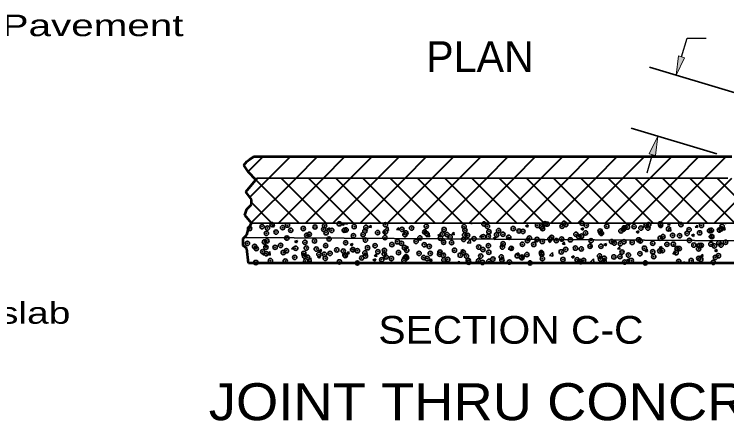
# Model space of a CAD drawing. Extents: x 14 to 49.3, y 28 to 50.
# Drawn here: x 24.379 to 29.004, y 39.461 to 42.098 of the extents above; entities that cross this region are included whole.
import ezdxf

# ---------------------------------------------------------------- set-up
doc = ezdxf.new("R2010")
doc.units = 0
doc.header["$LTSCALE"] = 0.056
doc.header["$PDMODE"] = 32
doc.header["$PDSIZE"] = 0.028
for name, color, linetype, lineweight in [('1', 7, 'Continuous', 35), ('3', 7, 'Continuous', 13), ('6', 7, 'Continuous', 13)]:
    doc.layers.add(name, color=color, linetype=linetype, lineweight=lineweight)

msp = doc.modelspace()

# ---------------------------------------------------------------- hatches: boundary and pattern name
at = {"layer": '1'}
for points in [[(28.72983, 41.81658), (28.68992, 41.8285), (28.67417, 41.70283), (28.67417, 41.70283)], [(28.54042, 41.18158), (28.5005, 41.1935), (28.55617, 41.30733), (28.55617, 41.30733)]]:
    msp.add_hatch(color=256, dxfattribs=at).paths.add_polyline_path(points)

# ---------------------------------------------------------------- linework, layer by layer
at = {"layer": '1', "lineweight": 25}
for p, q in [((28.70983, 41.82258), (28.74558, 41.94233)), ((28.74558, 41.94233), (28.87058, 41.94233)), ((28.52042, 41.1875), (28.48467, 41.06775))]:
    msp.add_line(p, q, dxfattribs=at)
at = {"layer": '1'}
for p, q in [((29.05775, 41.58833), (28.50167, 41.75425)), ((28.93975, 41.19292), (28.38367, 41.35875)), ((25.95442, 41.0355), (29.01067, 41.0355)), ((25.91817, 40.74367), (29.60692, 40.74367)), ((26.0495, 40.72508), (26.067, 40.73183)), ((26.0495, 40.72508), (26.06192, 40.71675)), ((26.06192, 40.71675), (26.067, 40.73183)), ((26.40875, 40.70508), (26.42625, 40.71183)), ((26.40875, 40.70508), (26.42117, 40.69675)), ((26.42117, 40.69675), (26.42625, 40.71183)), ((26.50217, 40.73208), (26.51192, 40.74367)), ((26.50217, 40.73208), (26.51708, 40.73075)), ((26.51708, 40.73075), (26.51475, 40.74367)), ((26.518, 40.73992), (26.5215, 40.74367)), ((26.518, 40.73992), (26.54025, 40.7365)), ((26.54025, 40.7365), (26.53942, 40.74367)), ((26.6815, 40.71633), (26.6935, 40.73075)), ((26.6815, 40.71633), (26.69642, 40.71508)), ((26.69642, 40.71508), (26.6935, 40.73075)), ((26.78475, 40.69858), (26.80425, 40.71883)), ((26.807, 40.69508), (26.80425, 40.71883)), ((26.86083, 40.70067), (26.87283, 40.715)), ((26.86083, 40.70067), (26.87575, 40.69933)), ((26.87575, 40.69933), (26.87283, 40.715)), ((27.34042, 40.74367), (27.34983, 40.73733)), ((27.34983, 40.73733), (27.35192, 40.74367)), ((27.69667, 40.72567), (27.71417, 40.73242)), ((27.69667, 40.72567), (27.70908, 40.71725)), ((27.70908, 40.71725), (27.71417, 40.73242)), ((28.05592, 40.70567), (28.07342, 40.71233)), ((28.05592, 40.70567), (28.06842, 40.69725)), ((28.06842, 40.69725), (28.0735, 40.71233)), ((28.3525, 40.73517), (28.36058, 40.74367)), ((28.3525, 40.73517), (28.37475, 40.73175)), ((28.37475, 40.73175), (28.37333, 40.74367)), ((28.61925, 40.73183), (28.62917, 40.74367)), ((28.61925, 40.73183), (28.63417, 40.7305)), ((28.61933, 40.69383), (28.63875, 40.71408)), ((28.63417, 40.7305), (28.63175, 40.74367)), ((28.64158, 40.69033), (28.63875, 40.71408)), ((28.79858, 40.71617), (28.81058, 40.7305)), ((28.79858, 40.71617), (28.8135, 40.71483)), ((28.8135, 40.71483), (28.81058, 40.7305)), ((28.97792, 40.7005), (28.98992, 40.71483)), ((28.97792, 40.7005), (28.99283, 40.69917)), ((28.98842, 40.74367), (28.997, 40.73783)), ((28.99283, 40.69917), (28.98992, 40.71483)), ((28.997, 40.73783), (28.99892, 40.74367)), ((26.76808, 40.68508), (26.78558, 40.69183)), ((26.76808, 40.68508), (26.7805, 40.67667)), ((26.7805, 40.67667), (26.78558, 40.69183)), ((26.78475, 40.69858), (26.807, 40.69508)), ((27.04008, 40.685), (27.05217, 40.69933)), ((27.04008, 40.685), (27.05508, 40.68367)), ((27.05158, 40.65717), (27.07108, 40.6775)), ((27.05158, 40.65717), (27.07383, 40.65375)), ((27.05508, 40.68367), (27.05217, 40.69933)), ((27.07383, 40.65375), (27.07108, 40.6775)), ((27.12733, 40.66508), (27.14483, 40.67175)), ((27.12733, 40.66508), (27.13975, 40.65667)), ((27.13975, 40.65667), (27.14483, 40.67175)), ((27.21942, 40.66933), (27.2315, 40.68367)), ((27.21942, 40.66933), (27.23433, 40.668)), ((27.23433, 40.668), (27.2315, 40.68367)), ((27.39875, 40.65358), (27.41075, 40.668)), ((27.39875, 40.65358), (27.41367, 40.65233)), ((27.41367, 40.65233), (27.41083, 40.668)), ((28.41525, 40.68558), (28.43275, 40.69233)), ((28.41525, 40.68558), (28.42767, 40.67725)), ((28.42767, 40.67725), (28.43275, 40.69233)), ((28.61933, 40.69383), (28.64158, 40.69033)), ((28.7745, 40.66558), (28.792, 40.67233)), ((28.7745, 40.66558), (28.78692, 40.65725)), ((28.78692, 40.65725), (28.792, 40.67233)), ((28.88617, 40.65242), (28.90558, 40.67275)), ((28.90833, 40.649), (28.90558, 40.67275)), ((29.36217, 40.62683), (25.87033, 40.64908)), ((26.19875, 40.6245), (26.21625, 40.63117)), ((26.19875, 40.6245), (26.21117, 40.61608)), ((26.21117, 40.61608), (26.21625, 40.63117)), ((26.558, 40.60442), (26.5755, 40.61117)), ((26.57042, 40.59608), (26.5755, 40.61117)), ((27.31842, 40.61583), (27.33792, 40.63608)), ((27.31842, 40.61583), (27.34067, 40.61233)), ((27.34067, 40.61233), (27.33792, 40.63608)), ((27.48658, 40.645), (27.50408, 40.65175)), ((27.48658, 40.645), (27.49908, 40.63667)), ((27.49908, 40.63667), (27.50408, 40.65175)), ((27.57808, 40.63792), (27.59008, 40.65225)), ((27.57808, 40.63792), (27.593, 40.63658)), ((27.593, 40.63658), (27.59008, 40.65225)), ((27.75733, 40.62225), (27.76942, 40.63658)), ((27.75733, 40.62225), (27.77233, 40.62092)), ((27.77233, 40.62092), (27.76942, 40.63658)), ((27.84592, 40.625), (27.86342, 40.63175)), ((27.84592, 40.625), (27.85833, 40.61667)), ((27.85833, 40.61658), (27.86342, 40.63175)), ((27.93667, 40.60658), (27.94875, 40.62092)), ((27.95167, 40.60525), (27.94875, 40.62092)), ((28.20517, 40.605), (28.22267, 40.61175)), ((28.21758, 40.59658), (28.22267, 40.61167)), ((28.88617, 40.65242), (28.90833, 40.649)), ((25.99892, 40.59108), (26.01092, 40.60542)), ((25.99892, 40.59108), (26.01383, 40.58975)), ((26.01383, 40.58975), (26.011, 40.60542)), ((26.17825, 40.57542), (26.19025, 40.58975)), ((26.17825, 40.57542), (26.19317, 40.57408)), ((26.19317, 40.57408), (26.19025, 40.58975)), ((26.3575, 40.55967), (26.36958, 40.57408)), ((26.3725, 40.55842), (26.36958, 40.57408)), ((26.558, 40.60442), (26.57042, 40.59608)), ((26.91725, 40.58442), (26.93475, 40.59117)), ((26.91725, 40.58442), (26.92975, 40.576)), ((26.92975, 40.576), (26.93475, 40.59117)), ((27.27658, 40.56442), (27.29408, 40.57108)), ((27.27658, 40.56442), (27.289, 40.556)), ((27.289, 40.556), (27.29408, 40.57108)), ((27.58525, 40.57442), (27.60467, 40.59475)), ((27.58525, 40.57442), (27.60742, 40.571)), ((27.60742, 40.571), (27.60467, 40.59475)), ((27.93667, 40.60658), (27.95158, 40.60525)), ((28.116, 40.59083), (28.12808, 40.60525)), ((28.116, 40.59083), (28.13092, 40.58958)), ((28.13092, 40.58958), (28.12808, 40.60525)), ((28.20517, 40.605), (28.21758, 40.59658)), ((28.29533, 40.57517), (28.30733, 40.5895)), ((28.29533, 40.57517), (28.31025, 40.57383)), ((28.31025, 40.57383), (28.30733, 40.5895)), ((28.47467, 40.5595), (28.48667, 40.57383)), ((28.48958, 40.55817), (28.48667, 40.57383)), ((28.5645, 40.585), (28.582, 40.59167)), ((28.5645, 40.585), (28.57692, 40.57658)), ((28.57692, 40.57658), (28.582, 40.59167)), ((28.92375, 40.56492), (28.94125, 40.57167)), ((28.92375, 40.56492), (28.93617, 40.55658)), ((28.93617, 40.55658), (28.94125, 40.57167)), ((25.98867, 40.54383), (26.00617, 40.55058)), ((25.98867, 40.54383), (26.00108, 40.53542)), ((26.00108, 40.53542), (26.00617, 40.55058)), ((26.0175, 40.53783), (26.037, 40.55808)), ((26.0175, 40.53783), (26.03975, 40.53433)), ((26.03975, 40.53433), (26.037, 40.55808)), ((26.28433, 40.49642), (26.30375, 40.51675)), ((26.30658, 40.493), (26.30375, 40.51675)), ((26.34792, 40.52383), (26.36542, 40.5305)), ((26.34792, 40.52383), (26.36033, 40.51542)), ((26.3575, 40.55967), (26.3725, 40.55842)), ((26.36033, 40.51542), (26.36542, 40.5305)), ((26.53683, 40.544), (26.54892, 40.55833)), ((26.53683, 40.544), (26.55183, 40.54267)), ((26.55183, 40.54267), (26.54892, 40.55833)), ((26.71617, 40.52833), (26.72825, 40.54267)), ((26.71617, 40.52833), (26.73108, 40.527)), ((26.73108, 40.527), (26.72825, 40.54267)), ((26.8955, 40.51267), (26.9075, 40.527)), ((26.91042, 40.51133), (26.9075, 40.527)), ((27.63583, 40.54442), (27.65333, 40.55108)), ((27.63583, 40.54442), (27.64825, 40.536)), ((27.64825, 40.536), (27.65333, 40.55108)), ((27.852, 40.53308), (27.8715, 40.55333)), ((27.852, 40.53308), (27.87425, 40.52958)), ((27.87425, 40.52958), (27.8715, 40.55333)), ((27.99508, 40.52433), (28.01267, 40.53108)), ((27.99508, 40.52433), (28.00758, 40.516)), ((28.00758, 40.516), (28.01267, 40.53108)), ((28.47467, 40.5595), (28.48958, 40.55817)), ((28.65392, 40.54383), (28.666, 40.55817)), ((28.65392, 40.54383), (28.66892, 40.5425)), ((28.66892, 40.5425), (28.666, 40.55817)), ((28.83325, 40.52808), (28.84533, 40.5425)), ((28.83325, 40.52808), (28.84817, 40.52683)), ((28.84817, 40.52683), (28.84533, 40.5425)), ((26.28433, 40.49642), (26.30658, 40.493)), ((26.70725, 40.50383), (26.72475, 40.5105)), ((26.70725, 40.50383), (26.71967, 40.49542)), ((26.71967, 40.49542), (26.72475, 40.5105)), ((26.71967, 40.49542), (26.72475, 40.5105)), ((26.8955, 40.51267), (26.91042, 40.51133)), ((27.0665, 40.48375), (27.084, 40.4905)), ((27.0665, 40.48375), (27.06683, 40.48358)), ((27.07483, 40.49692), (27.08683, 40.51133)), ((27.07483, 40.49692), (27.08975, 40.49567)), ((27.08167, 40.48358), (27.084, 40.4905)), ((27.08975, 40.49567), (27.08683, 40.51133)), ((27.256, 40.48358), (27.26617, 40.49558)), ((27.26842, 40.48358), (27.26617, 40.49558)), ((28.11883, 40.49167), (28.13833, 40.512)), ((28.11883, 40.49167), (28.14108, 40.48825)), ((28.14108, 40.48825), (28.13833, 40.512)), ((28.35442, 40.50433), (28.37192, 40.51108)), ((28.35442, 40.50433), (28.36683, 40.49592)), ((28.36683, 40.49592), (28.37192, 40.51108)), ((28.71367, 40.48433), (28.73117, 40.491)), ((28.71367, 40.48433), (28.71483, 40.48358)), ((28.72867, 40.48358), (28.73117, 40.491))]:
    msp.add_line(p, q, dxfattribs=at)
at = {"layer": '1', "lineweight": 40}
for p, q in [((25.89717, 41.07775), (25.99442, 41.175)), ((26.03167, 41.0355), (26.17125, 41.175)), ((26.20842, 41.0355), (26.348, 41.175)), ((26.38525, 41.0355), (26.52475, 41.175)), ((26.562, 41.0355), (26.70158, 41.175)), ((26.73875, 41.0355), (26.87833, 41.175)), ((26.91558, 41.0355), (27.05508, 41.175)), ((27.09233, 41.0355), (27.23192, 41.175)), ((27.26908, 41.0355), (27.40867, 41.175)), ((27.44592, 41.0355), (27.58542, 41.175)), ((27.62267, 41.0355), (27.76225, 41.175)), ((27.79942, 41.0355), (27.939, 41.175)), ((27.97625, 41.0355), (28.11575, 41.175)), ((28.153, 41.0355), (28.29258, 41.175)), ((28.32975, 41.0355), (28.46933, 41.175)), ((28.5065, 41.0355), (28.64608, 41.175)), ((28.68333, 41.0355), (28.82292, 41.175)), ((28.86008, 41.0355), (28.99967, 41.175)), ((25.90725, 40.91108), (26.03167, 41.0355)), ((25.91742, 40.7445), (26.20842, 41.0355)), ((26.227, 40.74367), (25.94575, 41.02483)), ((26.09342, 40.74367), (26.38525, 41.0355)), ((26.40375, 40.74367), (26.11192, 41.0355)), ((26.27017, 40.74367), (26.562, 41.0355)), ((26.5805, 40.74367), (26.28875, 41.0355)), ((26.44692, 40.74367), (26.73875, 41.0355)), ((26.75733, 40.74367), (26.4655, 41.0355)), ((26.62375, 40.74367), (26.91558, 41.0355)), ((26.93408, 40.74367), (26.64225, 41.0355)), ((26.8005, 40.74367), (27.09233, 41.0355)), ((27.11083, 40.74367), (26.819, 41.0355)), ((26.97725, 40.74367), (27.26908, 41.0355)), ((27.28767, 40.74367), (26.99583, 41.0355)), ((27.15408, 40.74367), (27.44592, 41.0355)), ((27.46442, 40.74367), (27.17258, 41.0355)), ((27.33083, 40.74367), (27.62267, 41.0355)), ((27.64117, 40.74367), (27.34933, 41.0355)), ((27.50758, 40.74367), (27.79942, 41.0355)), ((27.818, 40.74367), (27.52617, 41.0355)), ((27.68442, 40.74367), (27.97625, 41.0355)), ((27.99475, 40.74367), (27.70292, 41.0355)), ((27.86117, 40.74367), (28.153, 41.0355)), ((28.1715, 40.74367), (27.87967, 41.0355)), ((28.03792, 40.74367), (28.32975, 41.0355)), ((28.34833, 40.74367), (28.0565, 41.0355)), ((28.21475, 40.74367), (28.5065, 41.0355)), ((28.52508, 40.74367), (28.23325, 41.0355)), ((28.3915, 40.74367), (28.68333, 41.0355)), ((28.70183, 40.74367), (28.41, 41.0355)), ((28.56825, 40.74367), (28.86008, 41.0355)), ((28.87867, 40.74367), (28.58683, 41.0355)), ((28.74508, 40.74367), (29.03683, 41.0355)), ((29.05542, 40.74367), (28.76358, 41.0355)), ((28.92183, 40.74367), (29.21367, 41.0355)), ((29.23217, 40.74367), (28.94033, 41.0355)), ((26.05017, 40.74367), (25.91817, 40.87575))]:
    msp.add_line(p, q, dxfattribs=at)
at = {"layer": '1', "lineweight": 53}
for p, q in [((25.906, 41.156), (25.93625, 41.17508)), ((25.93625, 41.17508), (29.03592, 41.17508)), ((25.86975, 41.118), (25.88792, 41.14333)), ((25.9, 41.07358), (25.86975, 41.118)), ((25.88792, 41.14333), (25.906, 41.156)), ((25.94575, 41.02492), (25.9, 41.07358)), ((25.88183, 40.94667), (25.95442, 41.0355)), ((25.91817, 40.89592), (25.88183, 40.94667)), ((25.91817, 40.86425), (25.91817, 40.89592)), ((25.88792, 40.8325), (25.91817, 40.86425)), ((25.87583, 40.79442), (25.88792, 40.8325)), ((25.91817, 40.74367), (25.87583, 40.79442)), ((25.88792, 40.66758), (25.9, 40.70558)), ((25.9, 40.70558), (25.91817, 40.74367)), ((25.86375, 40.64217), (25.88792, 40.66758)), ((25.86375, 40.59775), (25.86375, 40.64217)), ((25.88792, 40.57875), (25.86375, 40.59775)), ((25.9, 40.48358), (25.88792, 40.57875)), ((29.60692, 40.48358), (25.9, 40.48358))]:
    msp.add_line(p, q, dxfattribs=at)
at = {"layer": '1', "lineweight": 13}
for points in [[(28.72983, 41.81658), (28.68992, 41.8285), (28.67417, 41.70283), (28.67417, 41.70283)], [(28.54042, 41.18158), (28.5005, 41.1935), (28.55617, 41.30733), (28.55617, 41.30733)]]:
    msp.add_lwpolyline(points, close=True, dxfattribs=at)
at = {"layer": '1'}
for p in [(26.05217, 40.73317), (26.48808, 40.7385), (26.7875, 40.73242), (27.42717, 40.73792), (27.82467, 40.73942), (27.83758, 40.73625), (27.94675, 40.74192), (27.95808, 40.73375), (28.06475, 40.74175), (28.49683, 40.73317), (28.57267, 40.73917), (28.70617, 40.7335), (25.90633, 40.70817), (25.98725, 40.71917), (26.02158, 40.71092), (26.12075, 40.71358), (26.15142, 40.72967), (26.17292, 40.697), (26.25417, 40.70792), (26.33075, 40.71783), (26.38767, 40.70225), (26.39342, 40.726), (26.43925, 40.69575), (26.52108, 40.69667), (26.53283, 40.69883), (26.585, 40.72075), (26.65458, 40.691), (26.66125, 40.71642), (26.89533, 40.70217), (26.95792, 40.71042), (27.05258, 40.72292), (27.16892, 40.7015), (27.29883, 40.72025), (27.30367, 40.69675), (27.4495, 40.72175), (27.45992, 40.68658), (27.5225, 40.69483), (27.61717, 40.70725), (27.65517, 40.69183), (27.68025, 40.68942), (27.775, 40.72808), (27.801, 40.71692), (27.80858, 40.707), (27.93483, 40.723), (28.09158, 40.72808), (28.18167, 40.69167), (28.225, 40.7225), (28.31633, 40.69217), (28.33383, 40.7045), (28.33958, 40.71242), (28.3585, 40.71683), (28.40217, 40.72067), (28.44617, 40.71092), (28.47967, 40.7295), (28.49192, 40.71117), (28.5745, 40.7285), (28.62542, 40.70558), (28.75883, 40.69992), (28.83958, 40.72783), (28.89233, 40.69425), (28.90408, 40.69683), (28.956, 40.69758), (28.96667, 40.70508), (28.97308, 40.72225), (26.01567, 40.67633), (26.07825, 40.68458), (26.14767, 40.64567), (26.14842, 40.64642), (26.27675, 40.66408), (26.29342, 40.67067), (26.403, 40.68008), (26.42233, 40.63992), (26.58017, 40.66067), (26.64275, 40.66892), (26.73742, 40.68142), (26.7845, 40.64917), (26.788, 40.68533), (26.91433, 40.66792), (26.9215, 40.67975), (27.01208, 40.64667), (27.04267, 40.6855), (27.05492, 40.67408), (27.14475, 40.64508), (27.15792, 40.67167), (27.18842, 40.66842), (27.20733, 40.65333), (27.302, 40.66575), (27.32183, 40.66283), (27.36358, 40.64183), (27.42408, 40.65467), (27.45533, 40.65717), (27.50942, 40.66683), (27.55042, 40.67067), (27.58875, 40.6515), (27.72225, 40.64592), (27.85567, 40.64025), (27.8665, 40.65017), (27.93183, 40.63983), (28.02442, 40.67092), (28.04225, 40.65442), (28.06167, 40.6585), (28.087, 40.67917), (28.18808, 40.6795), (28.19, 40.67617), (28.5715, 40.64525), (28.589, 40.65533), (28.65158, 40.66358), (28.69775, 40.66125), (28.74625, 40.676), (28.82758, 40.68), (28.90667, 40.65542), (25.89225, 40.61167), (26.00183, 40.62067), (26.0185, 40.62767), (26.10717, 40.59842), (26.265, 40.61917), (26.32758, 40.62742), (26.4, 40.59683), (26.52983, 40.61558), (26.65817, 40.63317), (26.7205, 40.59658), (26.82958, 40.60358), (26.86625, 40.62167), (26.89217, 40.61183), (26.98683, 40.62425), (27.03967, 40.60233), (27.16592, 40.61833), (27.21775, 40.61683), (27.29575, 40.63708), (27.45667, 40.59617), (27.55142, 40.60867), (27.67717, 40.60617), (27.70925, 40.62942), (27.75067, 40.60442), (27.77183, 40.63767), (27.80558, 40.62375), (27.89642, 40.62942), (27.98908, 40.63458), (28.12258, 40.629), (28.256, 40.62333), (28.27383, 40.61383), (28.31325, 40.60892), (28.33642, 40.62208), (28.3895, 40.61767), (28.43108, 40.6345), (28.44308, 40.62767), (28.52292, 40.61208), (28.61508, 40.60542), (28.65642, 40.60642), (28.76092, 40.63042), (28.78983, 40.60075), (28.82458, 40.59683), (28.83833, 40.59817), (28.90092, 40.60642), (28.92333, 40.59517), (28.95292, 40.61442), (28.96658, 40.6005), (28.99558, 40.61892), (25.93858, 40.59142), (25.94983, 40.57767), (25.99133, 40.55783), (26.01242, 40.58592), (26.07208, 40.58583), (26.12475, 40.55225), (26.14533, 40.56325), (26.2055, 40.58017), (26.27367, 40.58083), (26.339, 40.5745), (26.47242, 40.56892), (26.51442, 40.56208), (26.57467, 40.57158), (26.577, 40.57033), (26.60592, 40.56325), (26.65517, 40.54992), (26.67167, 40.58275), (26.73933, 40.55758), (26.78142, 40.566), (26.87283, 40.552), (26.91125, 40.58467), (26.92617, 40.56675), (27.072, 40.59175), (27.1415, 40.55467), (27.23625, 40.56717), (27.29275, 40.55383), (27.39408, 40.58792), (27.42108, 40.57142), (27.45908, 40.55433), (27.54733, 40.58742), (27.60483, 40.57933), (27.80075, 40.55158), (27.92875, 40.55658), (27.95867, 40.57233), (28.02125, 40.58058), (28.05867, 40.57533), (28.11592, 40.593), (28.187, 40.59292), (28.3235, 40.55533), (28.46933, 40.58033), (28.52317, 40.55675), (28.56842, 40.56208), (28.58575, 40.56492), (28.675, 40.5505), (28.6805, 40.57742), (28.69475, 40.57808), (28.82083, 40.5755), (26.0155, 40.5445), (26.19925, 40.52058), (26.25825, 40.54658), (26.26183, 40.52883), (26.28308, 40.5215), (26.3565, 40.54133), (26.39167, 40.54092), (26.39692, 40.51358), (26.42892, 40.54658), (26.52517, 40.53533), (26.52675, 40.53233), (26.63458, 40.51667), (26.65858, 40.52967), (26.76383, 40.505), (26.78042, 40.54175), (26.79208, 40.524), (26.82642, 40.51325), (26.90825, 40.5015), (26.92108, 40.52567), (26.9255, 40.51842), (27.00625, 40.54633), (27.03658, 40.51908), (27.059, 40.51275), (27.07892, 40.5465), (27.13967, 40.54067), (27.16283, 40.53508), (27.1675, 40.50425), (27.19242, 40.50708), (27.27317, 40.53508), (27.31325, 40.52933), (27.32583, 40.5015), (27.40658, 40.52942), (27.48558, 40.51008), (27.54008, 40.52375), (27.54433, 40.50425), (27.6435, 40.53083), (27.6735, 40.51817), (27.67417, 40.523), (27.70608, 40.53908), (27.8025, 40.54058), (27.807, 40.5125), (27.94042, 40.50683), (28.03192, 40.50525), (28.07392, 40.50125), (28.17775, 40.53033), (28.18392, 40.50967), (28.20808, 40.51525), (28.27067, 40.5235), (28.31025, 40.52567), (28.36533, 40.53592), (28.44008, 40.54442), (28.52925, 40.5255), (28.8215, 40.51358), (28.83517, 40.50783), (28.92983, 40.52033), (28.94992, 40.53117), (25.94667, 40.48733), (26.04133, 40.49983), (26.13733, 40.4965), (26.27067, 40.49758), (26.48883, 40.49167), (26.60592, 40.48417), (27.32833, 40.48933), (27.39092, 40.49758), (27.418, 40.48825), (27.45933, 40.49583), (27.59275, 40.49017), (27.72625, 40.48458), (28.05017, 40.49442), (28.05558, 40.49208), (28.20733, 40.49558), (28.34083, 40.48992), (28.38342, 40.50042), (28.47425, 40.48433), (28.69167, 40.49483), (28.77258, 40.49958), (28.91625, 40.488)]:
    msp.add_point(p, dxfattribs=at)
at = {"layer": '6'}
for p, q in [((28.67417, 41.70283), (28.67425, 41.70283)), ((28.99967, 41.175), (28.99975, 41.175))]:
    msp.add_line(p, q, dxfattribs=at)

# ---------------------------------------------------------------- texts
at = {"layer": '3'}
for s, height, width, p in [('Concrete Pavement', 0.14, 1.4, (23.16058, 41.95625)), ('Concrete Subslab', 0.14, 1.35, (22.73392, 40.09017)), ('SECTION C-C', 0.18, 1.1, (26.74208, 39.96042)), ('JOINT THRU CONCRETE', 0.24, 1.1, (25.641, 39.464))]:
    msp.add_text(s, height=height, dxfattribs=dict(at, width=width)).set_placement(p)
msp.add_text('PLAN', height=0.2, dxfattribs=at).set_placement((27.05233, 41.72367))

doc.saveas('drawing.dxf')
